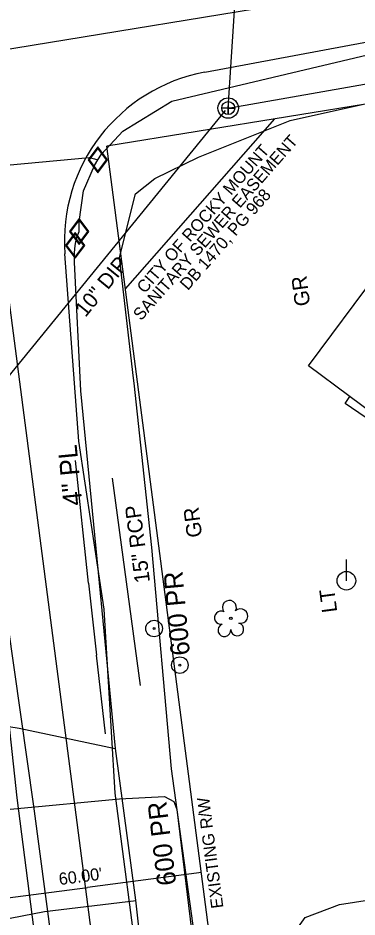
# Model space of a CAD drawing. Extents: x 2364404 to 2371833, y 798876 to 809754.
# Drawn here: x 2368392.4 to 2368481.7, y 807723.1 to 807960.2 of the extents above; entities that cross this region are included whole.
import ezdxf

# ---------------------------------------------------------------- set-up
doc = ezdxf.new("R2010")
doc.units = 0
for name, color, linetype in [('Exist Building', 7, 'Continuous'), ('Exist Other Culture Area Outline', 7, 'Continuous'), ('Exist Other Culture Located Object CELL', 7, 'Continuous'), ('Exist Right of Way Easement Line', 7, 'Continuous'), ('Exist Right of Way Easement Line Text', 7, 'Continuous'), ('Exist Right of Way Line', 7, 'Continuous'), ('Exist Right of Way Line Text', 7, 'Continuous'), ('Exist Right of Way Width CELL', 7, 'Continuous'), ('Exist Roads EOP', 7, 'Continuous'), ('Exist Roads EOT', 7, 'Continuous'), ('Exist Roads Soil Text', 7, 'Continuous'), ('Exist Structure Minor Pipes RCP 15 Inch', 7, 'Continuous'), ('Exist Structure Minor Pipes RCP 15 Inch Text', 7, 'Continuous'), ('Exist Utilities Gas UG Line SUE LOS B', 7, 'Continuous'), ('Exist Utilities Gas UG Line SUE LOS B Text', 7, 'Continuous'), ('Exist Utilities Gas Valve CELL', 7, 'Continuous'), ('Exist Utilities Power Pole CELL', 7, 'Continuous'), ('Exist Utilities Power Pole Text', 7, 'Continuous'), ('Exist Utilities Sanitary Sewer Manhole CELL', 7, 'Continuous'), ('Exist Utilities Sanitary Sewer Manhole Leader', 7, 'Continuous'), ('Exist Utilities Sanitary Sewer UG Line', 7, 'Continuous'), ('Exist Utilities Sanitary Sewer UG Line Text', 7, 'Continuous'), ('Exist Utilities Telephone UG Cable SUE LOS C', 7, 'Continuous'), ('Exist Utilities Telephone UG Cable SUE LOS C Text', 7, 'Continuous'), ('Exist Vegetation Tree CELL', 7, 'Continuous'), ('Exist Vegetation Woods Line', 7, 'Continuous'), ('Prop Horizontal Alignment', 7, 'Continuous')]:
    doc.layers.add(name, color=color, linetype=linetype)

msp = doc.modelspace()

# ---------------------------------------------------------------- linework, layer by layer
at = {"layer": 'Exist Building'}
msp.add_lwpolyline([(2368511.5, 807836.82), (2368468.97, 807868.46), (2368487.15, 807892.9), (2368530.01, 807861.01), (2368519.78, 807847.26), (2368522.76, 807845.03), (2368515.24, 807834.92), (2368511.92, 807837.39)], close=True, dxfattribs=at)
at = {"layer": 'Exist Other Culture Area Outline'}
msp.add_lwpolyline([(2368534.06, 807851.56), (2368517.74, 807830.18), (2368508.71, 807837), (2368490.82, 807850.22), (2368478.59, 807858.58), (2368479.85, 807860.37)], dxfattribs=at)
at = {"layer": 'Exist Other Culture Located Object CELL'}
for centre, radius in [((2368428.26, 807799.21), 2.18), ((2368428.26, 807799.21), 0.24), ((2368435.06, 807789.56), 2.18), ((2368435.06, 807789.56), 0.24)]:
    msp.add_circle(centre, radius, dxfattribs=at)
at = {"layer": 'Exist Right of Way Easement Line'}
msp.add_line((2368420.71, 807888.81), (2368460.07, 807933.67), dxfattribs=at)
at = {"layer": 'Exist Right of Way Line'}
for p in [(2368975.69, 808017.56), (2368552.49, 806875.84)]:
    msp.add_line(p, (2368415.81, 807926.44), dxfattribs=at)
at = {"layer": 'Exist Right of Way Width CELL'}
for p in [(2368440.73, 807734.87), (2368381.24, 807727.13)]:
    msp.add_line(p, (2368410.73, 807730.96), dxfattribs=at)
at = {"layer": 'Exist Roads EOP'}
for points in [[(2368441.67, 807945.95), (2368496.73, 807956.25)], [(2368458.85, 807273.24), (2368452.4, 807323.88), (2368446.15, 807368.12), (2368444.02, 807369.35), (2368441.6, 807369.34), (2368439.16, 807392.12), (2368442.82, 807396.21), (2368435.2, 807454.89), (2368429.11, 807503.15), (2368423.49, 807547.61), (2368418.51, 807586.84), (2368409.79, 807654.27), (2368402.88, 807704.72), (2368396.58, 807752.35), (2368389.7, 807800.7), (2368383.01, 807844.61), (2368373.21, 807897.74)], [(2368479.96, 807275.52), (2368472.82, 807329.17), (2368467.3, 807372.73), (2368463.49, 807399.04), (2368455.99, 807457.89), (2368450.28, 807505.61), (2368444.32, 807550.36), (2368439.14, 807589.77), (2368430.88, 807657.09), (2368424.4, 807706.96), (2368418, 807755.78), (2368415.07, 807804.32), (2368408.4, 807848.6), (2368404.75, 807897.99)]]:
    msp.add_lwpolyline(points, dxfattribs=at)
msp.add_arc((2368450.01, 807901.33), 45.39, 100.5964, 184.2291, dxfattribs=at)
at = {"layer": 'Exist Roads EOT'}
for p, q in [((2368411.01, 807811.17), (2368407.51, 807843.54)), ((2368411.01, 807811.17), (2368413.05, 807792.15)), ((2368415.5, 807771.48), (2368413.05, 807792.15))]:
    msp.add_line(p, q, dxfattribs=at)
at = {"layer": 'Exist Structure Minor Pipes RCP 15 Inch'}
for q in [(2368417.29, 807838.9), (2368424.66, 807784.21)]:
    msp.add_line((2368424.66, 807784.21), q, dxfattribs=at)
at = {"layer": 'Exist Utilities Gas UG Line SUE LOS B'}
for points in [[(2368407.49, 807900.26), (2368407.83, 807902.19), (2368408.5, 807903.92), (2368408.48, 807906.42), (2368409.65, 807914.64), (2368412.56, 807921.31), (2368413.42, 807922.79), (2368414.43, 807924.35), (2368420.02, 807930.36), (2368432.93, 807938.29), (2368511.16, 807956.83), (2368547.75, 807963.81), (2368550.91, 807964.29), (2368560.32, 807966.83), (2368577.66, 807970.81), (2368609.45, 807976.23), (2368658.87, 807983.56), (2368707.95, 807991.52), (2368757.5, 808000.06), (2368807.07, 808007.66), (2368820.71, 808009.46), (2368856.81, 808014.26), (2368905.45, 808022.91)], [(2367870.54, 807838.09), (2367919.9, 807848.3), (2367968.48, 807855.53), (2368019.02, 807864.91), (2368064.26, 807872.88), (2368067.9, 807873.62), (2368094.51, 807877.58), (2368117.72, 807881.71), (2368161.92, 807888.8), (2368216.03, 807898.12), (2368260.65, 807907.32), (2368261.62, 807907.37), (2368282.45, 807912.12), (2368324.46, 807917.31), (2368347.86, 807919.04), (2368361.63, 807920.36), (2368385.5, 807921.08), (2368411.16, 807923.46), (2368412.54, 807923.08), (2368413.42, 807922.79)], [(2368482.33, 807269.18), (2368476.59, 807310.66), (2368475.28, 807318.93), (2368469.46, 807367.86), (2368462.89, 807417.28), (2368456.74, 807466.98), (2368452.98, 807496.64), (2368450.66, 807516.79), (2368444.57, 807565.67), (2368442.07, 807583.58), (2368437.6, 807615.09), (2368434.95, 807636.28), (2368430.96, 807664.36), (2368426.87, 807696.93), (2368423.49, 807727.61), (2368418.1, 807767.6), (2368413.6, 807813.99), (2368409, 807861.86), (2368407.26, 807895.83), (2368407.32, 807898.29), (2368407.49, 807900.26)], [(2368310.7, 807783.48), (2368322.09, 807776.05), (2368356.42, 807776.96), (2368373.04, 807776.09), (2368392.7, 807772.95), (2368418.02, 807767.61), (2368418.1, 807767.6)], [(2368313.04, 807721.47), (2368322.92, 807724.14), (2368337.41, 807724.42), (2368370.5, 807719.38), (2368384.38, 807721.69), (2368399.38, 807724.6), (2368423.5, 807727.46)]]:
    msp.add_lwpolyline(points, dxfattribs=at)
at = {"layer": 'Exist Utilities Gas Valve CELL'}
for p, q in [((2368413.42, 807922.79), (2368413.42, 807922.79)), ((2368408.5, 807903.92), (2368408.5, 807903.92)), ((2368407.49, 807900.26), (2368407.49, 807900.26))]:
    msp.add_line(p, q, dxfattribs=at)
for points in [[(2368413.42, 807926.21), (2368410.89, 807922.79), (2368413.42, 807919.38), (2368415.96, 807922.79), (2368413.42, 807926.21)], [(2368408.5, 807907.33), (2368405.96, 807903.92), (2368408.5, 807900.51), (2368411.04, 807903.92), (2368408.5, 807907.33)], [(2368407.49, 807903.67), (2368404.96, 807900.26), (2368407.49, 807896.85), (2368410.03, 807900.26), (2368407.49, 807903.67)]]:
    msp.add_lwpolyline(points, dxfattribs=at)
for points in [[(2368415.71, 807922.79), (2368413.42, 807925.87), (2368411.14, 807922.79), (2368413.42, 807919.72)], [(2368410.79, 807903.92), (2368408.5, 807907), (2368406.21, 807903.92), (2368408.5, 807900.84)], [(2368409.78, 807900.26), (2368407.49, 807903.34), (2368405.21, 807900.26), (2368407.49, 807897.18)]]:
    msp.add_lwpolyline(points, close=True, dxfattribs=at)
at = {"layer": 'Exist Utilities Power Pole CELL'}
for q in [(2368478.94, 807817.43), (2368478.94, 807811.81)]:
    msp.add_line((2368478.94, 807811.81), q, dxfattribs=at)
msp.add_circle((2368478.94, 807811.81), 2.45, dxfattribs=at)
at = {"layer": 'Exist Utilities Sanitary Sewer Manhole CELL'}
msp.add_lwpolyline([(2368447.79, 807938.18), (2368447.79, 807934.75), (2368447.79, 807936.47), (2368449.51, 807936.47), (2368446.08, 807936.47)], dxfattribs=at)
for radius in [2.69, 1.71]:
    msp.add_circle((2368447.79, 807936.47), radius, dxfattribs=at)
at = {"layer": 'Exist Utilities Sanitary Sewer Manhole Leader'}
msp.add_lwpolyline([(2368447.79, 807936.47), (2368451.77, 807997.32), (2368451.26, 808001.19)], dxfattribs=at)
at = {"layer": 'Exist Utilities Sanitary Sewer UG Line'}
for p, q in [((2368448.77, 807936.62), (2368803.21, 807999.04)), ((2368351.33, 807818.39), (2368447.04, 807935.85))]:
    msp.add_line(p, q, dxfattribs=at)
at = {"layer": 'Exist Utilities Telephone UG Cable SUE LOS C'}
for points in [[(2368447.65, 807703.43), (2368446.8, 807704.73), (2368443.71, 807705.62), (2368441.34, 807707.5), (2368439.57, 807713.21), (2368432.89, 807762.22), (2368427.64, 807820.62), (2368422.99, 807863.94), (2368422.84, 807865.23), (2368419.19, 807897.08), (2368423.33, 807913.84), (2368428.48, 807917.87), (2368439.93, 807923.49), (2368464.13, 807933.23), (2368512.68, 807944.02), (2368549.48, 807954.52), (2368556.19, 807957.85), (2368561.77, 807963.18), (2368601.39, 807970.6), (2368605.77, 807969.06), (2368611.88, 807962.94), (2368614.19, 807962.49)], [(2368389.8, 807477.23), (2368411.52, 807479.13), (2368426.75, 807483.79), (2368423.25, 807515.6), (2368416.95, 807563.1), (2368411.16, 807611.97), (2368408.13, 807633.66), (2368404.45, 807661.14), (2368400.96, 807692.3), (2368397.77, 807710.8), (2368392.17, 807754.58), (2368386.02, 807810.85), (2368379.04, 807858.46), (2368375.16, 807879.37), (2368367.44, 807903.09), (2368362.27, 807911.13), (2368354.75, 807913.38)], [(2368377.99, 807750.39), (2368378.69, 807750.5), (2368391.34, 807751.66), (2368419.15, 807754.32), (2368431.04, 807754.95), (2368433.45, 807753.62), (2368434.27, 807751.51), (2368438.9, 807713.2), (2368440.77, 807707.31), (2368443.34, 807704.96), (2368446.84, 807703.95), (2368447.34, 807703.99)]]:
    msp.add_lwpolyline(points, dxfattribs=at)
at = {"layer": 'Exist Vegetation Tree CELL'}
msp.add_line((2368448.49, 807801.89), (2368448.49, 807801.89), dxfattribs=at)
msp.add_circle((2368448.49, 807801.89), 0.326, dxfattribs=at)
for centre, radius, start, end in [((2368448.11, 807804.77), 1.86, 330.1651, 219.7134), ((2368445.89, 807802.05), 1.73, 62.6636, 279.3457), ((2368451.04, 807802.48), 1.9, 257.1011, 134.1999), ((2368446.79, 807798.77), 1.69, 111.5671, 6.231), ((2368450.17, 807798.99), 1.7, 181.2822, 74.56)]:
    msp.add_arc(centre, radius, start, end, dxfattribs=at)
at = {"layer": 'Exist Vegetation Woods Line'}
msp.add_lwpolyline([(2368577.22, 807720.54), (2368546.57, 807715.08), (2368510.61, 807710.16), (2368489.85, 807709.24), (2368479.44, 807709.34), (2368471.54, 807711.27), (2368465.82, 807714.49), (2368464.84, 807718.4), (2368468.11, 807723), (2368477.11, 807726.45), (2368487.83, 807728.13), (2368496.39, 807731.38), (2368504.76, 807732.15), (2368514.62, 807730.34), (2368529.14, 807727.79), (2368541.4, 807729.47), (2368575.86, 807735.29)], dxfattribs=at)
at = {"layer": 'Prop Horizontal Alignment'}
for p, q in [((2368427.27, 807599.89), (2368315.24, 808460.34)), ((2368381.6, 807950.7), (2368895.64, 808034.91))]:
    msp.add_line(p, q, dxfattribs=at)

# ---------------------------------------------------------------- texts
at = {"layer": 'Exist Right of Way Easement Line Text'}
for s, p in [('SANITARY SEWER EASEMENT', (2368424.83, 807880.22)), ('CITY OF ROCKY MOUNT', (2368425.79, 807887.39)), ('DB 1470, PG 968', (2368437.16, 807888.21))]:
    msp.add_text(s, height=3.2, rotation=48.739, dxfattribs=at).set_placement(p)
at = {"layer": 'Exist Right of Way Line Text'}
msp.add_text('EXISTING R/W', height=3.2, rotation=97.4124, dxfattribs=at).set_placement((2368446.54, 807725.61))
at = {"layer": 'Exist Right of Way Width CELL'}
msp.add_text("60.00'", height=3.2, rotation=7.4124, dxfattribs=at).set_placement((2368403.36, 807731.54))
at = {"layer": 'Exist Roads Soil Text'}
for p in [(2368469.42, 807884.49), (2368440.96, 807823.48)]:
    msp.add_text('GR', height=4, rotation=97.4798, dxfattribs=at).set_placement(p)
at = {"layer": 'Exist Structure Minor Pipes RCP 15 Inch Text'}
msp.add_text('15" RCP', height=4, rotation=97.4798, dxfattribs=at).set_placement((2368427.2, 807811.5))
at = {"layer": 'Exist Utilities Gas UG Line SUE LOS B Text'}
msp.add_text('4" PL', height=5, rotation=95.4886, dxfattribs=at).set_placement((2368409.38, 807831.82))
at = {"layer": 'Exist Utilities Power Pole Text'}
msp.add_text('LT', height=4, rotation=97.4798, dxfattribs=at).set_placement((2368476.54, 807803.65))
at = {"layer": 'Exist Utilities Sanitary Sewer UG Line Text'}
msp.add_text('10" DIP', height=4, rotation=50.8253, dxfattribs=at).set_placement((2368410.17, 807881.11))
at = {"layer": 'Exist Utilities Telephone UG Cable SUE LOS C Text'}
for rotation, p in [(95.1351, (2368437.71, 807792.31)), (96.8969, (2368434.14, 807731.73))]:
    msp.add_text('600 PR', height=5, rotation=rotation, dxfattribs=at).set_placement(p)

doc.saveas('drawing.dxf')
